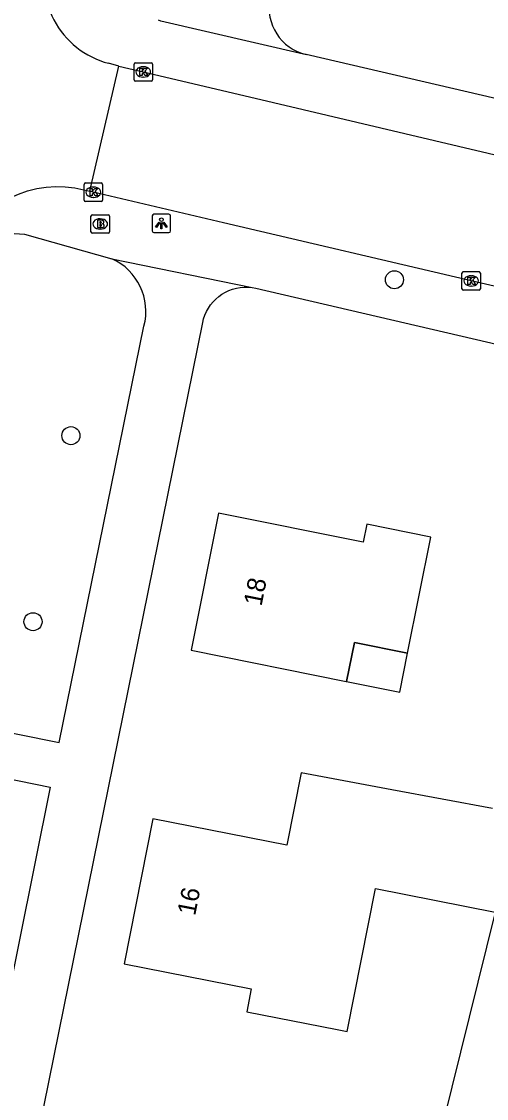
# Model space of a CAD drawing. Extents: x 162186 to 163152, y 385513 to 386513.
# Drawn here: x 162520.4 to 162545.7, y 385896.5 to 385954.9 of the extents above; entities that cross this region are included whole.
import ezdxf

# ---------------------------------------------------------------- set-up
doc = ezdxf.new("R2010")
doc.units = 0
for name, color, linetype in [('IMGEO_Boom', 7, 'Continuous'), ('IMGEO_Brandkraan', 7, 'Continuous'), ('IMGEO_Kolk', 7, 'Continuous'), ('IMGEO_Lichtpunt', 7, 'Continuous'), ('IMGEO_Pand', 7, 'Continuous'), ('IMGEO_Pand_nummerreeks', 7, 'Continuous'), ('IMGEO_Pand_overbouw', 7, 'Continuous'), ('IMGEO_Rijbaan_lokaal_open', 7, 'Continuous'), ('IMGEO_Voetpad_open', 7, 'Continuous')]:
    doc.layers.add(name, color=color, linetype=linetype)

msp = doc.modelspace()

# ---------------------------------------------------------------- linework, layer by layer
at = {"layer": 'IMGEO_Boom'}
for centre in [(162540.657, 385940.913), (162523.094, 385932.453), (162521.038, 385922.361)]:
    msp.add_circle(centre, 0.489, dxfattribs=at)
at = {"layer": 'IMGEO_Brandkraan'}
for p, q in [((162524.185, 385943.511), (162524.185, 385944.363)), ((162524.26, 385944.437), (162525.112, 385944.437)), ((162525.186, 385944.363), (162525.186, 385943.511)), ((162524.696, 385943.657), (162524.671, 385943.657)), ((162524.673, 385944.217), (162524.698, 385944.217)), ((162525.112, 385943.437), (162524.26, 385943.437))]:
    msp.add_line(p, q, dxfattribs=at)
for points in [[(162524.185, 385943.511), (162524.185, 385944.363)], [(162524.26, 385944.437), (162525.112, 385944.437)], [(162525.186, 385944.363), (162525.186, 385943.511)], [(162524.533, 385944.137), (162524.533, 385943.737), (162524.746, 385943.737)], [(162524.764, 385944.137), (162524.533, 385944.137)], [(162524.712, 385944.056), (162524.658, 385944.056), (162524.658, 385943.98)], [(162524.658, 385943.98), (162524.711, 385943.98)], [(162524.72, 385943.904), (162524.658, 385943.904), (162524.658, 385943.823)], [(162524.658, 385943.823), (162524.72, 385943.823)], [(162525.112, 385943.437), (162524.26, 385943.437)]]:
    msp.add_lwpolyline(points, dxfattribs=at)
for centre, radius, start, end in [((162524.262, 385944.361), 0.0765, 91.55205, 178.44795), ((162524.262, 385944.361), 0.0765, 91.55205, 178.44795), ((162525.11, 385944.361), 0.0765, 1.55205, 88.44795), ((162525.11, 385944.361), 0.0765, 1.55205, 88.44795), ((162524.713, 385944.018), 0.0379, 267.82845, 90.93552), ((162524.721, 385943.863), 0.0404, 269.87594, 90.50774), ((162524.752, 385943.988), 0.251, 268.66757, 293.53466), ((162524.768, 385943.992), 0.145, 59.4692, 91.53667), ((162524.793, 385944.039), 0.0922, 285.51372, 58.15012), ((162524.798, 385943.847), 0.105, 301.31148, 78.98903), ((162524.262, 385943.513), 0.0765, 181.55205, 268.44795), ((162524.262, 385943.513), 0.0765, 181.55205, 268.44795), ((162525.11, 385943.513), 0.0765, 271.55205, 358.44795), ((162525.11, 385943.513), 0.0765, 271.55205, 358.44795)]:
    msp.add_arc(centre, radius, start, end, dxfattribs=at)
for centre, major_axis, ratio, start_param, end_param in [((162524.672, 385943.937), (-0.387, 0.002), 0.722429, 4.712389, 7.853982), ((162524.697, 385943.937), (-0.39, 0.002), 0.717154, 1.570796, 4.712389)]:
    msp.add_ellipse(centre, major_axis=major_axis, ratio=ratio, start_param=start_param, end_param=end_param, dxfattribs=at)
at = {"layer": 'IMGEO_Kolk'}
for p, q in [((162526.52, 385951.758), (162526.52, 385952.61)), ((162526.595, 385952.684), (162527.447, 385952.684)), ((162527.008, 385952.464), (162527.033, 385952.464)), ((162527.521, 385952.61), (162527.521, 385951.758)), ((162527.031, 385951.904), (162527.006, 385951.904)), ((162527.447, 385951.684), (162526.595, 385951.684)), ((162523.814, 385945.234), (162523.814, 385946.086)), ((162523.889, 385946.16), (162524.741, 385946.16)), ((162524.815, 385946.086), (162524.815, 385945.234)), ((162524.302, 385945.94), (162524.327, 385945.94)), ((162524.741, 385945.16), (162523.889, 385945.16)), ((162524.325, 385945.38), (162524.3, 385945.38)), ((162544.394, 385941.351), (162545.246, 385941.351)), ((162544.319, 385940.425), (162544.319, 385941.277)), ((162544.807, 385941.131), (162544.832, 385941.131)), ((162545.32, 385941.277), (162545.32, 385940.425)), ((162545.246, 385940.351), (162544.394, 385940.351)), ((162544.83, 385940.571), (162544.805, 385940.571))]:
    msp.add_line(p, q, dxfattribs=at)
for points in [[(162526.52, 385951.758), (162526.52, 385952.61)], [(162526.595, 385952.684), (162527.447, 385952.684)], [(162527.521, 385952.61), (162527.521, 385951.758)], [(162526.841, 385952.384), (162526.964, 385952.384), (162526.964, 385952.233), (162527.094, 385952.384), (162527.258, 385952.384), (162527.112, 385952.233), (162527.265, 385951.984), (162527.113, 385951.984), (162527.028, 385952.148), (162526.964, 385952.081), (162526.964, 385951.984), (162526.841, 385951.984), (162526.841, 385952.384)], [(162527.447, 385951.684), (162526.595, 385951.684)], [(162523.814, 385945.234), (162523.814, 385946.086)], [(162523.889, 385946.16), (162524.741, 385946.16)], [(162524.815, 385946.086), (162524.815, 385945.234)], [(162524.135, 385945.86), (162524.258, 385945.86), (162524.258, 385945.709), (162524.388, 385945.86), (162524.552, 385945.86), (162524.406, 385945.709), (162524.559, 385945.46), (162524.407, 385945.46), (162524.322, 385945.624), (162524.258, 385945.557), (162524.258, 385945.46), (162524.135, 385945.46), (162524.135, 385945.86)], [(162524.741, 385945.16), (162523.889, 385945.16)], [(162544.394, 385941.351), (162545.246, 385941.351)], [(162544.319, 385940.425), (162544.319, 385941.277)], [(162544.64, 385941.051), (162544.763, 385941.051), (162544.763, 385940.9), (162544.893, 385941.051), (162545.057, 385941.051), (162544.911, 385940.9), (162545.064, 385940.651), (162544.912, 385940.651), (162544.827, 385940.815), (162544.763, 385940.748), (162544.763, 385940.651), (162544.64, 385940.651), (162544.64, 385941.051)], [(162545.32, 385941.277), (162545.32, 385940.425)], [(162545.246, 385940.351), (162544.394, 385940.351)]]:
    msp.add_lwpolyline(points, dxfattribs=at)
for centre, start, end in [((162526.597, 385952.608), 91.55205, 178.44795), ((162526.597, 385952.608), 91.55205, 178.44795), ((162527.445, 385952.608), 1.55205, 88.44795), ((162527.445, 385952.608), 1.55205, 88.44795), ((162526.597, 385951.76), 181.55205, 268.44795), ((162526.597, 385951.76), 181.55205, 268.44795), ((162527.445, 385951.76), 271.55205, 358.44795), ((162527.445, 385951.76), 271.55205, 358.44795), ((162523.891, 385946.084), 91.55205, 178.44795), ((162523.891, 385946.084), 91.55205, 178.44795), ((162524.739, 385946.084), 1.55205, 88.44795), ((162524.739, 385946.084), 1.55205, 88.44795), ((162523.891, 385945.236), 181.55205, 268.44795), ((162523.891, 385945.236), 181.55205, 268.44795), ((162524.739, 385945.236), 271.55205, 358.44795), ((162524.739, 385945.236), 271.55205, 358.44795), ((162544.396, 385941.275), 91.55205, 178.44795), ((162544.396, 385941.275), 91.55205, 178.44795), ((162545.244, 385941.275), 1.55205, 88.44795), ((162545.244, 385941.275), 1.55205, 88.44795), ((162544.396, 385940.427), 181.55205, 268.44795), ((162544.396, 385940.427), 181.55205, 268.44795), ((162545.244, 385940.427), 271.55205, 358.44795), ((162545.244, 385940.427), 271.55205, 358.44795)]:
    msp.add_arc(centre, 0.0765, start, end, dxfattribs=at)
for centre, major_axis, ratio, start_param, end_param in [((162527.007, 385952.184), (-0.387, 0.002), 0.722429, 4.712389, 7.853982), ((162527.032, 385952.184), (-0.39, 0.002), 0.717154, 1.570796, 4.712389), ((162524.301, 385945.66), (-0.387, 0.002), 0.722429, 4.712389, 7.853982), ((162524.326, 385945.66), (-0.39, 0.002), 0.717154, 1.570796, 4.712389), ((162544.806, 385940.851), (-0.387, 0.002), 0.722429, 4.712389, 7.853982), ((162544.831, 385940.851), (-0.39, 0.002), 0.717154, 1.570796, 4.712389)]:
    msp.add_ellipse(centre, major_axis=major_axis, ratio=ratio, start_param=start_param, end_param=end_param, dxfattribs=at)
at = {"layer": 'IMGEO_Lichtpunt'}
for p, q in [((162527.507, 385944.374), (162527.507, 385943.567)), ((162527.507, 385944.374), (162527.507, 385943.567)), ((162528.409, 385944.469), (162527.601, 385944.469)), ((162528.409, 385944.469), (162527.601, 385944.469)), ((162528.503, 385943.567), (162528.503, 385944.374)), ((162528.503, 385943.567), (162528.503, 385944.374)), ((162527.601, 385943.473), (162528.409, 385943.473)), ((162527.601, 385943.473), (162528.409, 385943.473))]:
    msp.add_line(p, q, dxfattribs=at)
for points in [[(162527.881, 385944.038), (162527.92, 385944.01), (162527.732, 385943.748), (162527.694, 385943.775), (162527.881, 385944.038)], [(162527.983, 385943.99), (162528.03, 385943.99), (162528.03, 385943.668), (162527.983, 385943.668), (162527.983, 385943.99)], [(162528.093, 385944.01), (162528.131, 385944.037), (162528.318, 385943.775), (162528.279, 385943.747), (162528.093, 385944.01)]]:
    msp.add_lwpolyline(points, dxfattribs=at)
msp.add_circle((162528.006, 385944.172), 0.0994, dxfattribs=at)
for centre, start, end in [((162527.601, 385944.374), 90, 180), ((162527.601, 385944.374), 90, 180), ((162528.409, 385944.374), 0, 90), ((162528.409, 385944.374), 0, 90), ((162527.601, 385943.567), 180, 270), ((162527.601, 385943.567), 180, 270), ((162528.409, 385943.567), 270, 0), ((162528.409, 385943.567), 270, 360)]:
    msp.add_arc(centre, 0.0946, start, end, dxfattribs=at)
at = {"layer": 'IMGEO_Pand'}
for points in [[(162542.631, 385926.955), (162539.161, 385927.651), (162538.966, 385926.675), (162531.11, 385928.249), (162529.62, 385920.812), (162538.039, 385919.124), (162538.062, 385919.12), (162538.485, 385921.231), (162541.368, 385920.653), (162542.631, 385926.955)], [(162545.981, 385912.22), (162540.515, 385913.238), (162535.599, 385914.154), (162534.824, 385910.229), (162527.537, 385911.667), (162525.985, 385903.797), (162532.879, 385902.436), (162532.635, 385901.201), (162537.541, 385900.233), (162538.096, 385900.124), (162539.627, 385907.888), (162546.121, 385906.607), (162542.837, 385893.318), (162546.87, 385892.49), (162548.07, 385897.93)]]:
    msp.add_lwpolyline(points, dxfattribs=at)
at = {"layer": 'IMGEO_Pand_overbouw'}
msp.add_lwpolyline([(162541.368, 385920.653), (162538.485, 385921.231), (162538.062, 385919.12), (162540.945, 385918.542)], close=True, dxfattribs=at)
at = {"layer": 'IMGEO_Rijbaan_lokaal_open'}
for points in [[(162524.119, 385945.725), (162525.704, 385952.501)], [(162525.704, 385952.501), (162525.139, 385952.653)], [(162525.704, 385952.501), (162527.021, 385952.183), (162532.79, 385950.827), (162547.044, 385947.477), (162556.704, 385945.23)], [(162516.788, 385941.593), (162516.868, 385941.882), (162517.042, 385942.369), (162517.258, 385942.839), (162517.515, 385943.287), (162517.811, 385943.711), (162518.144, 385944.107), (162518.511, 385944.471), (162518.91, 385944.801), (162519.335, 385945.094), (162519.786, 385945.348), (162520.257, 385945.561), (162520.746, 385945.731), (162521.247, 385945.856), (162521.758, 385945.936), (162522.274, 385945.97), (162522.791, 385945.958), (162523.305, 385945.9), (162524.119, 385945.725)], [(162553.537, 385938.828), (162544.816, 385940.852), (162531.374, 385944.005), (162524.311, 385945.661), (162524.119, 385945.725)]]:
    msp.add_lwpolyline(points, dxfattribs=at)
msp.add_arc((162526.337, 385957.208), 4.71, 160.469, 255.26283, dxfattribs=at)
at = {"layer": 'IMGEO_Voetpad_open'}
for points in [[(162535.867, 385953.127), (162535.719, 385953.15), (162527.976, 385954.947), (162527.847, 385954.989)], [(162750.77, 385903.177), (162747.115, 385904.027), (162535.867, 385953.127)], [(162517.331, 385941.462), (162517.44, 385941.711), (162517.57, 385941.95), (162517.721, 385942.176), (162517.891, 385942.387), (162518.08, 385942.583), (162518.286, 385942.76), (162518.506, 385942.919), (162518.74, 385943.057), (162518.985, 385943.174), (162519.24, 385943.269), (162519.502, 385943.34), (162519.77, 385943.388), (162520.04, 385943.412), (162520.312, 385943.411), (162520.583, 385943.386), (162525.32, 385942.052)], [(162525.32, 385942.052), (162532.931, 385940.487)], [(162517.573, 385876.141), (162530.251, 385938.589), (162530.298, 385938.782), (162530.366, 385938.984), (162530.452, 385939.18), (162530.556, 385939.367), (162530.675, 385939.545), (162530.81, 385939.71), (162530.959, 385939.864), (162531.122, 385940.003), (162531.296, 385940.127), (162531.48, 385940.235), (162531.673, 385940.326), (162531.874, 385940.4), (162532.081, 385940.455), (162532.291, 385940.492), (162532.504, 385940.509), (162532.718, 385940.508), (162532.931, 385940.487)], [(162532.931, 385940.487), (162533.141, 385940.448), (162742.31, 385891.809)], [(162510.922, 385918.649), (162511.59, 385917.99), (162522.449, 385915.81), (162527.062, 385938.387)], [(162509.855, 385915.132), (162511.153, 385915.582), (162521.961, 385913.391), (162518.56, 385896.553), (162505.684, 385899.141), (162505.196, 385899.591)]]:
    msp.add_lwpolyline(points, dxfattribs=at)
for centre, radius, start, end in [((162536.46, 385955.669), 2.611, 168.73919, 256.864), ((162524.015, 385939.185), 3.15, 345.32279, 65.52134)]:
    msp.add_arc(centre, radius, start, end, dxfattribs=at)

# ---------------------------------------------------------------- texts
at = {"layer": 'IMGEO_Pand_nummerreeks'}
for s, rotation, p in [('18', 78.67283, (162533.437, 385923.169)), ('16', 78.84416, (162529.837, 385906.376))]:
    msp.add_text(s, height=1, rotation=rotation, dxfattribs=at).set_placement(p)

doc.saveas('drawing.dxf')
